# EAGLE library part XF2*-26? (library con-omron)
OMRON FPC Connector Source : http://www.omron.com/ecb/products/pdf/fpc.pdf
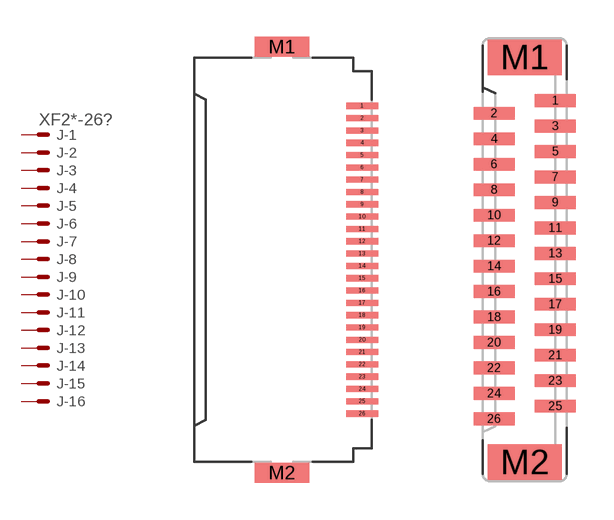
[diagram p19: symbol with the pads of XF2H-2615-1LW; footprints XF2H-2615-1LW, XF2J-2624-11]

Designator prefix J; gates -1=PV -2=P -3=P -4=P -5=P -6=P -7=P -8=P -9=P -10=P -11=P -12=P -13=P -14=P -15=P -16=P -17=P -18=P -19=P -20=P -21=P -22=P -23=P -24=P -25=P -26=P

## XF2H-2615-1LW (MF: OMRON COMPONENTS USA; MPN: XF2H-2615-1LW; OC_FARNELL: unknown; OC_NEWARK: 12J5143)  [XF2H-2615-1LW]
1  -1:MSV  pas
2  -2:MS  pas
3  -3:MS  pas
4  -4:MS  pas
5  -5:MS  pas
6  -6:MS  pas
7  -7:MS  pas
8  -8:MS  pas
9  -9:MS  pas
10  -10:MS  pas
11  -11:MS  pas
12  -12:MS  pas
13  -13:MS  pas
14  -14:MS  pas
15  -15:MS  pas
16  -16:MS  pas
17  -17:MS  pas
18  -18:MS  pas
19  -19:MS  pas
20  -20:MS  pas
21  -21:MS  pas
22  -22:MS  pas
23  -23:MS  pas
24  -24:MS  pas
25  -25:MS  pas
26  -26:MS  pas

## XF2J-2624-11 (MF: OMRON COMPONENTS USA; MPN: XF2J-2624-11; OC_FARNELL: unknown; OC_NEWARK: 89C8575)  [XF2J-2624-11]
Pads as for XF2H-2615-1LW

## XF2L-2625-1 (MPN: XF2L-2625-1; OC_FARNELL: unknown; OC_NEWARK: 37M0900)  [XF2L-2625-1]
Pads as for XF2H-2615-1LW

## Footprint XF2H-2615-1LW (pad centres in mm)
Standard Rotary Backlock Type (0.5 mm-pitch) Source : http://www.omron.com/ecb/products/pdf/fpc.pdf
smd 1.3 x 0.25: 1 3.175,6.25; 2 3.175,5.75; 3 3.175,5.25; 4 3.175,4.75; 5 3.175,4.25; 6 3.175,3.75; 7 3.175,3.25; 8 3.175,2.75; 9 3.175,2.25; 10 3.175,1.75; 11 3.175,1.25; 12 3.175,0.75; 13 3.175,0.25; 14 3.175,-0.25; 15 3.175,-0.75; 16 3.175,-1.25; 17 3.175,-1.75; 18 3.175,-2.25; 19 3.175,-2.75; 20 3.175,-3.25; 21 3.175,-3.75; 22 3.175,-4.25; 23 3.175,-4.75; 24 3.175,-5.25; 25 3.175,-5.75; 26 3.175,-6.25
smd 2.2 x 0.8: M1 -0.075,8.65; M2 -0.075,-8.65

## Footprint XF2J-2624-11 (pad centres in mm)
ZIF Slide-locking Type (0.5 mm-pitch) Standard Source : http://www.omron.com/ecb/products/pdf/fpc.pdf
smd 1.6 x 0.5: 1 1.2,6.25; 2 -1.2,5.75; 3 1.2,5.25; 4 -1.2,4.75; 5 1.2,4.25; 6 -1.2,3.75; 7 1.2,3.25; 8 -1.2,2.75; 9 1.2,2.25; 10 -1.2,1.75; 11 1.2,1.25; 12 -1.2,0.75; 13 1.2,0.25; 14 -1.2,-0.25; 15 1.2,-0.75; 16 -1.2,-1.25; 17 1.2,-1.75; 18 -1.2,-2.25; 19 1.2,-2.75; 20 -1.2,-3.25; 21 1.2,-3.75; 22 -1.2,-4.25; 23 1.2,-4.75; 24 -1.2,-5.25; 25 1.2,-5.75; 26 -1.2,-6.25
smd 2.9 x 1.4: M1 0,7.95; M2 0,-7.95

## Footprint XF2L-2625-1 (pad centres in mm)
ZIF Slide-locking Type (0.5 mm-pitch) Upper-contact Type Source : http://www.omron.com/ecb/products/pdf/fpc.pdf
smd 1 x 0.25: 1 1.905,6.25; 2 1.905,5.75; 3 1.905,5.25; 4 1.905,4.75; 5 1.905,4.25; 6 1.905,3.75; 7 1.905,3.25; 8 1.905,2.75; 9 1.905,2.25; 10 1.905,1.75; 11 1.905,1.25; 12 1.905,0.75; 13 1.905,0.25; 14 1.905,-0.25; 15 1.905,-0.75; 16 1.905,-1.25; 17 1.905,-1.75; 18 1.905,-2.25; 19 1.905,-2.75; 20 1.905,-3.25; 21 1.905,-3.75; 22 1.905,-4.25; 23 1.905,-4.75; 24 1.905,-5.25; 25 1.905,-5.75; 26 1.905,-6.25
smd 1.34 x 1: M1 0.18,8.637; M2 0.18,-8.637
